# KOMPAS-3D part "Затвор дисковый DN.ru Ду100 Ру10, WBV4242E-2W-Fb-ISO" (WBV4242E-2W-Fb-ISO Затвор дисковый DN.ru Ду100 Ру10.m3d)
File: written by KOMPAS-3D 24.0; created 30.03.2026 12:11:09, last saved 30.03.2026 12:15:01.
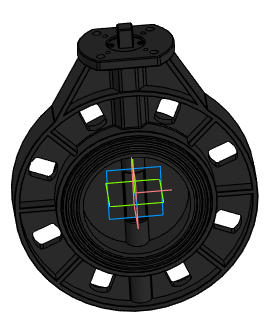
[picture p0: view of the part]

Document properties: Автор: R2D2; Полное имя файла: WBV4242E-2W-Fb-ISO Затвор дисковый DN.ru Ду100 Ру10.cdw

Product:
- Part/product: Затвор дисковый DN.ru Ду100 Ру10  | designation WBV4242E-2W-Fb-ISO
    Масса: 2.02
    Раздел спецификации: Прочие изделия
    Форматы листов документа: A2
    Примечание: D050-81207

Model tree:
1. Операция без истории:2

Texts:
  WBV4242E-2W-Fb-ISO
